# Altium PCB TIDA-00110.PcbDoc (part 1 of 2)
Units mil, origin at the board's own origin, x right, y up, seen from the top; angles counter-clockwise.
Board outline 3543.31 x 1771.65 mil, 4 copper layers (Top Layer, L2_GND-PLANE, L3_PWR-PLANE, Bottom Layer), stack 90 mil thick; 191 components, 98 nets, 449 pads, 138 vias.
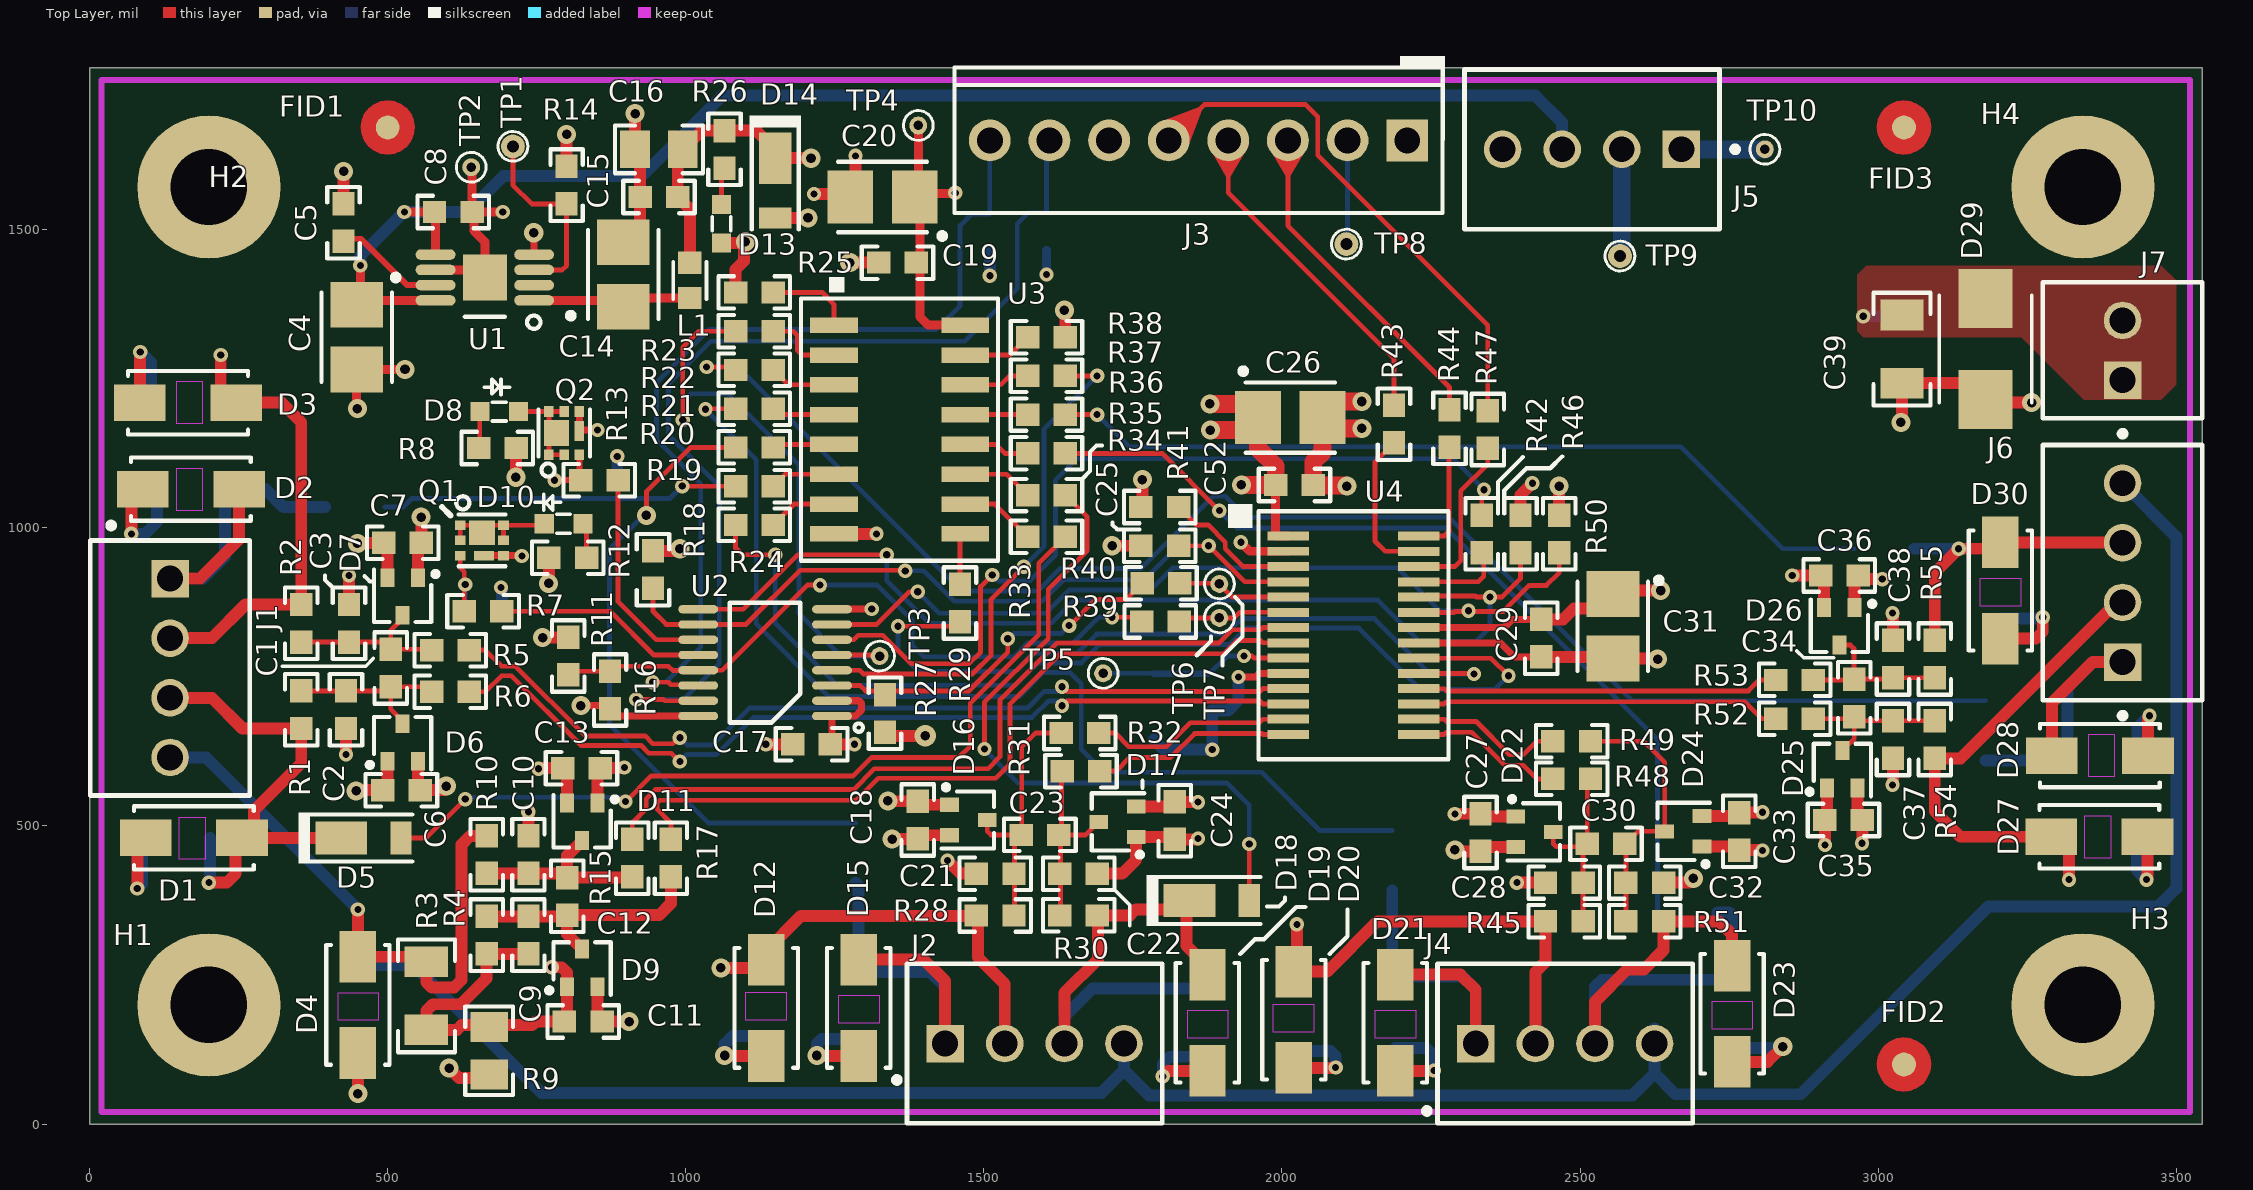
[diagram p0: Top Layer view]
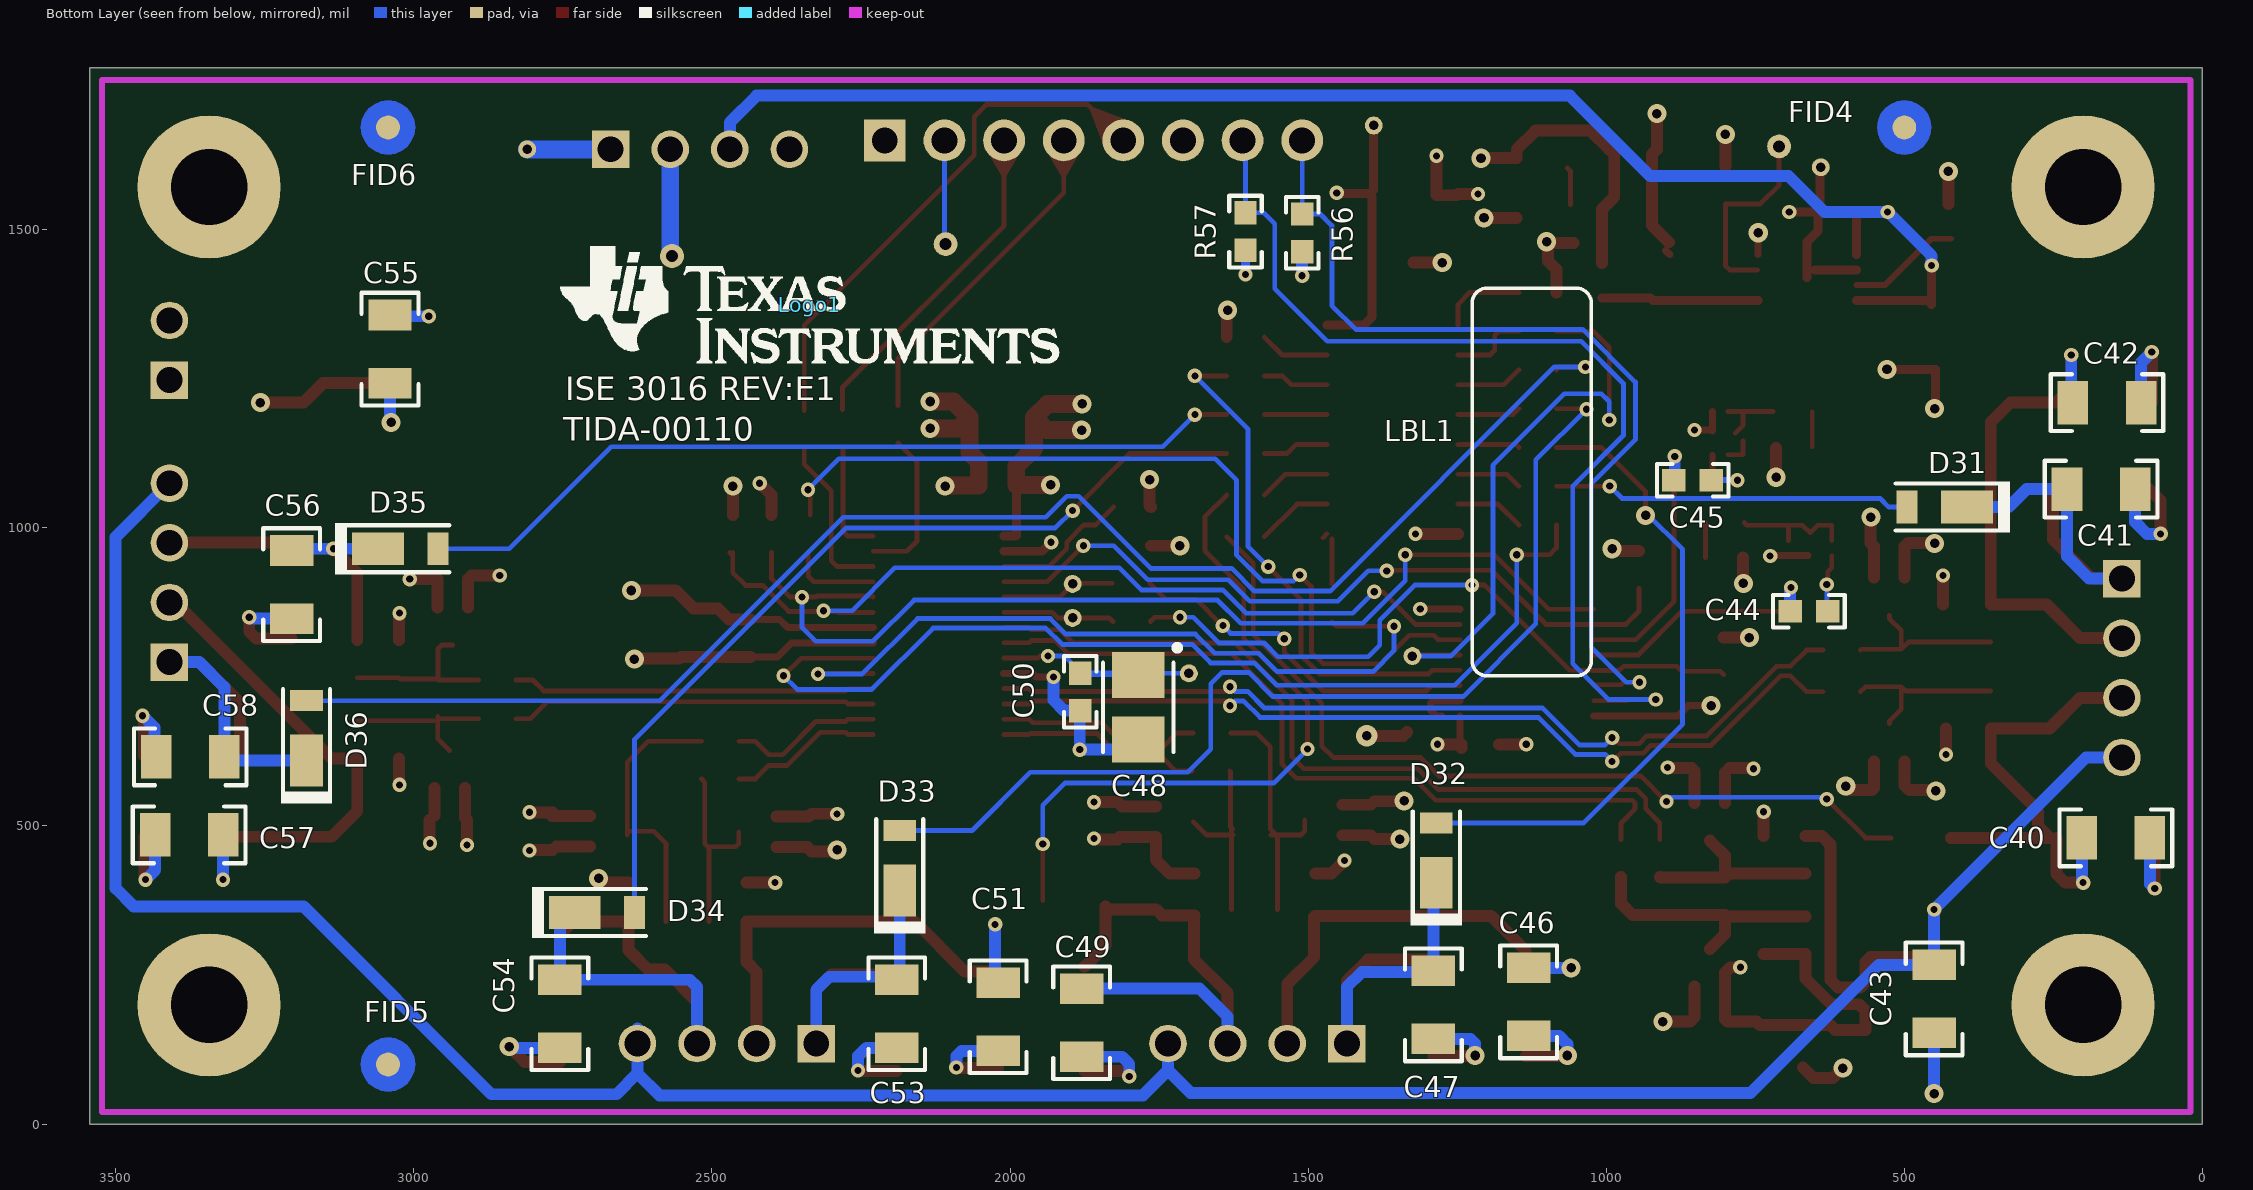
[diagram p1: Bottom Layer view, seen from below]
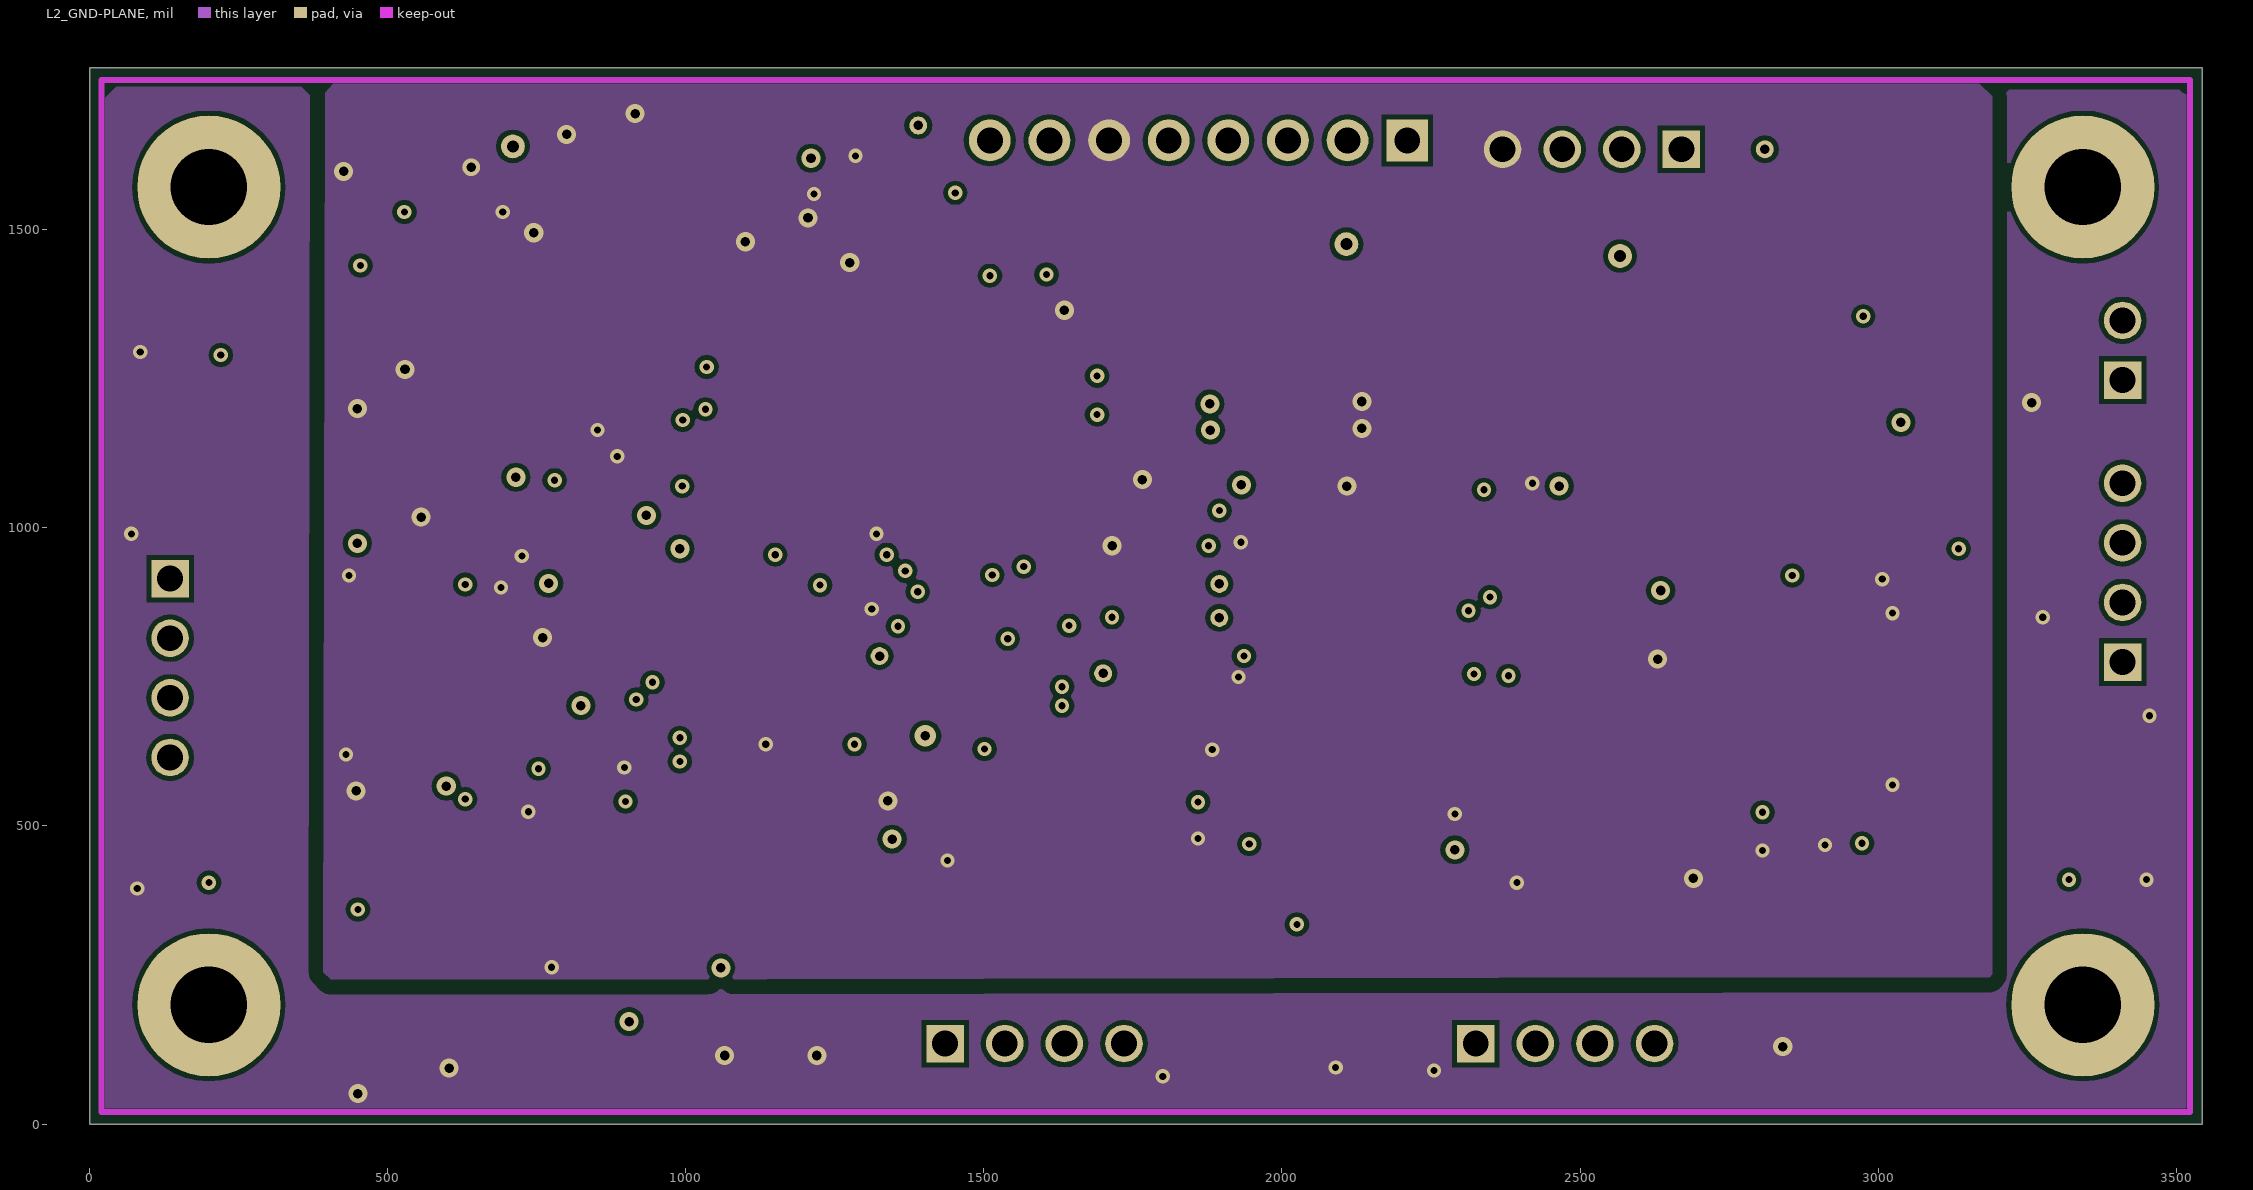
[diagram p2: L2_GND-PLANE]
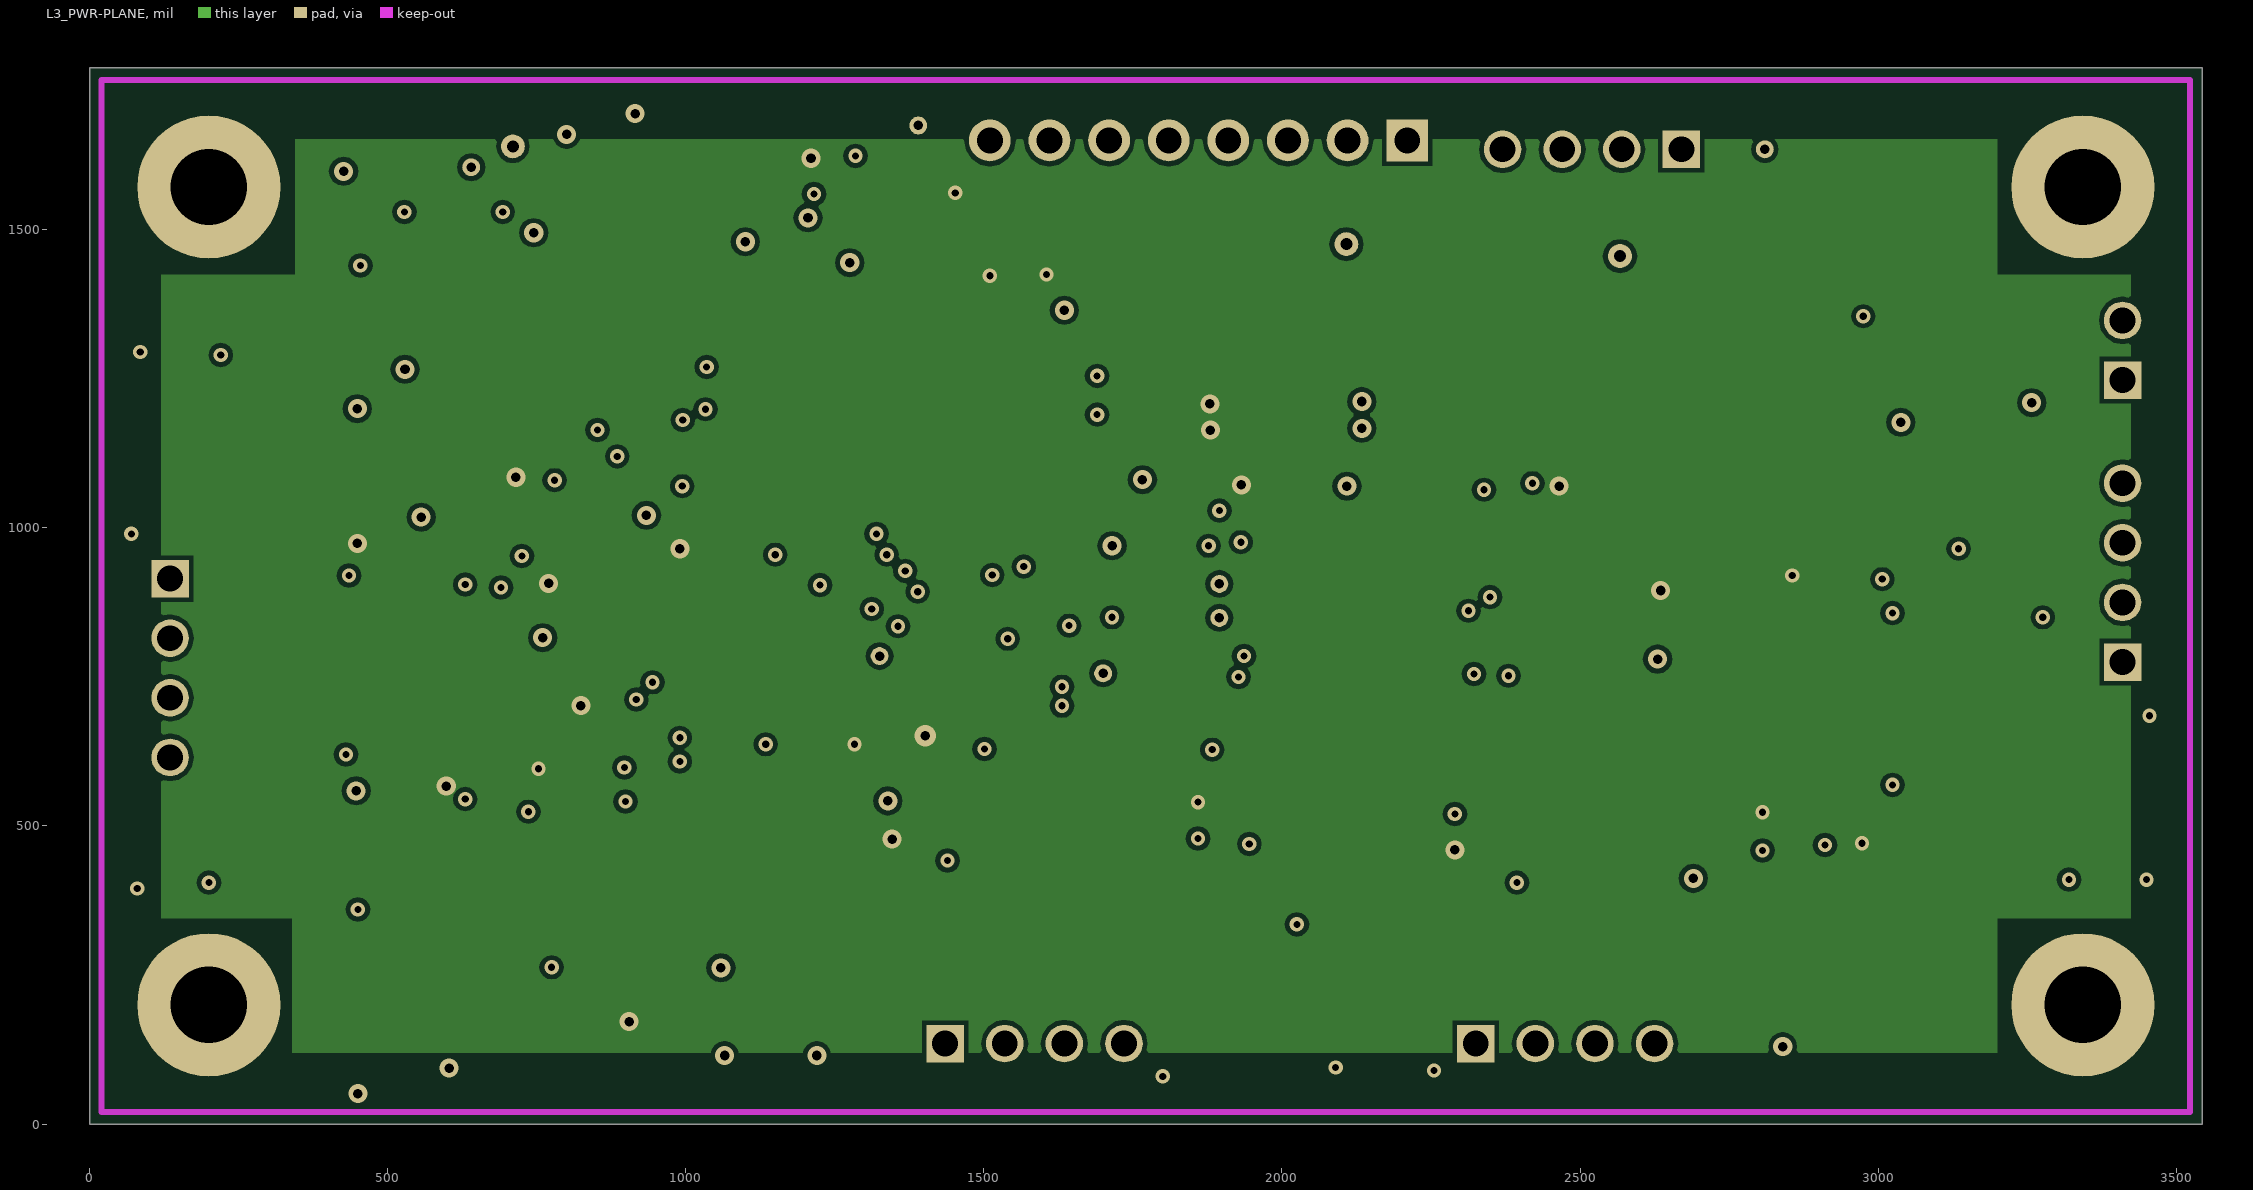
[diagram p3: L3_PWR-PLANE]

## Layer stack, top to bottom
Top Layer: signal copper 1.4
Dielectric: core 59.2, FR-4, Dk 4.8
L2_GND-PLANE: signal copper 1.4
Dielectric: prepreg 12.6, FR-4, Dk 4.8
L3_PWR-PLANE: signal copper 1.4
Dielectric: core 12.6, FR-4, Dk 4.8
Bottom Layer: signal copper 1.4

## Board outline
0,0 0,1771.65 3543.31,1771.65 3543.31,0

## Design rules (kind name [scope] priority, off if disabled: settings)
AcuteAngle [All] p1: minimum=4.50000000000000E+0001 checktracksonly=FALSE
AssemblyTestPointUsage [All] p1: valid=2
Clearance "Clearance_U1 Pad to Pad" [InPadClass('Less Than 7.7') vs InPadClass('Less Than 7.7')] p1: gap=7.7
Clearance Clearance_1 [InPolygon vs IsKeepOut] p2: gap=1
Clearance "Clearance_Poly to Poly" [InPolygon vs InPolygon] p3: gap=25
Clearance "Clearance_VIA TO VIA" [IsVia vs IsVia] p4: gap=8
Clearance "Clearance_Via to SMD" [IsVia vs IsSMTPin] p5: gap=8
Clearance Clearance_BoardEdge_MountingHoles [OnCopper and InComponentClass('Mounting Holes') vs IsKeepOut] p6: gap=20
Clearance Clearance_Poly [InPolygon vs IsTrack and IsVia and IsSMTPin and IsThruPin] p7: gap=15
Clearance [All] p8: gap=8
ComponentClearance ComponentClearance_Logo [InComponentClass('Logo')] p1: gap=50 collisioncheckmode=3 verticalgap=10 showdistances=FALSE
ComponentClearance ComponentClearance_ScrewToNut [(HasFootprint('NY PMS 440 0025 PH')) vs (HasFootprint('Keystone_1902C'))] p2: gap=5 collisioncheckmode=3 verticalgap=10 showdistances=FALSE
ComponentClearance ComponentClearance_MountingHoles [InComponentClass('Mounting Holes')] p3: gap=250 collisioncheckmode=3 verticalgap=100000 showdistances=FALSE
ComponentClearance ComponentClearance_SmallPassives [HasFootprint('0201*') or HasFootprint('0402*') or HasFootprint('0508') or HasFootprint('0603*') or HasFootprint('0612') or HasFootprint('0805*') or HasFootprint('0815*') or HasFootprint('0830*') or HasFootprint('1206*') or HasFootprint('1210*') or HasFootprint('1808*') or HasFootprint('1812*') or HasFootprint('1825*') or HasFootprint('2010*') or HasFootprint('2220*') or HasFootprint('2225*') or HasFootprint('2512*') or HasFootprint('2728*') or HasFootprint('3518*') vs HasFootprint('0201*') or HasFootprint('0402*') or HasFootprint('0508') or HasFootprint('0603*') or HasFootprint('0612') or HasFootprint('0805*') or HasFootprint('0815*') or HasFootprint('0830*') or HasFootprint('1206*') or HasFootprint('1210*') or HasFootprint('1808*') or HasFootprint('1812*') or HasFootprint('1825*') or HasFootprint('2010*') or HasFootprint('2220*') or HasFootprint('2225*') or HasFootprint('2512*') or HasFootprint('2728*') or HasFootprint('3518*')] p4: gap=20 collisioncheckmode=3 verticalgap=10 showdistances=FALSE
ComponentClearance ComponentClearance_THtoSMT [IsThruComponent vs IsSMTComponent] p5: gap=100 collisioncheckmode=3 verticalgap=30 showdistances=FALSE
ComponentClearance ComponentClearance_THtoTH [IsThruComponent vs IsThruComponent] p6: gap=118.11 collisioncheckmode=3 verticalgap=30 showdistances=FALSE
ComponentClearance [All] p7: gap=40 collisioncheckmode=3 verticalgap=10 showdistances=FALSE
DiffPairsRouting DiffPair_DiffPairsRouting [InDifferentialPair ('J1')] p1: maxlimit=10 minlimit=8 mostfreqgap=8 maxuncoupledlength=500
DiffPairsRouting [All] p2: maxlimit=100 minlimit=10 mostfreqgap=10 maxuncoupledlength=1000
FabricationTestPointUsage TestPointUsage [All] p1: valid=2 allowmultiple=FALSE
FabricationTestpoint Testpoint [All] p1: side=3 testpointundercomponent=TRUE minsize=40 maxsize=100 preferedsize=60 minholesize=0 maxholesize=40 preferedholesize=32 testpointgrid=1 allowsidetop=TRUE allowsidebottom=TRUE usegrid=TRUE gridtolerance=0.01
FanoutControl Fanout_LCC [IsLCC] p1: bgadir=Out bgaviamode=Centered fanoutstyle=Auto fanoutdirection=Alternating viagrid=1 // Fanout_LCC (Default Rule)
FanoutControl Fanout_BGA [IsBGA] p2: bgadir=Out bgaviamode=Centered fanoutstyle=Auto fanoutdirection=Alternating viagrid=1 // Fanout_BGA (Default Rule)
FanoutControl Fanout_Default [All] p4: bgadir=Out bgaviamode=Centered fanoutstyle=Auto fanoutdirection=Alternating viagrid=1 // Fanout_Default (Default Rule)
FanoutControl Fanout_Small [(CompPinCount < 5)] p5: bgadir=Out bgaviamode=Centered fanoutstyle=Auto fanoutdirection=OutThenIn viagrid=1 // Fanout_Small (Default Rule)
HoleSize [All] p1: absolutevalues=TRUE maxlimit=251 minlimit=7.8 maxpercent=80.000 minpercent=20.000
MatchedLengths DiffPair_MatchedLengths [InDifferentialPair ('J1')] p1: tolerance=1000 checknetsindiffpair=TRUE checkdiffpairvsdiffpair=TRUE checkothers=TRUE
MinimumAnnularRing MinimumAnnularRing_ThermalPadVias [IsVia and InAnyComponent] p1: minimumring=5.91
MinimumAnnularRing [All] p2: minimumring=6
MinimumSolderMaskSliver MinimumSolderMaskSliver_Logo [InComponentClass('Logo') vs InComponentClass('Logo')] p1: minsoldermaskwidth=0.7
MinimumSolderMaskSliver [All] p2: minsoldermaskwidth=3.94
PlaneClearance [All] p1: clearance=16
PlaneConnect [All] p1: planeconnectstyle=Direct reliefexpansion=10 reliefentries=4 reliefconductorwidth=10 reliefairgap=10
PolygonConnect [All] p1: connectstyle=Direct reliefconductorwidth=10 reliefentries=4 polygonreliefangle="90 Angle"
RoutingVias RoutingVias_PWR [InNetClass('PWR')] p1: holewidth=16 width=32 viastyle="Through Hole" minholewidth=12 minwidth=24 maxholewidth=20 maxwidth=40
RoutingVias [InNetClass('All Nets')] p2: holewidth=12 width=24 viastyle="Through Hole" minholewidth=12 minwidth=24 maxholewidth=20 maxwidth=40
RoutingVias ThermalPadVias [IsVia and InAnyComponent] p3: holewidth=7.87 width=19.68 viastyle="Through Hole" minholewidth=7.87 minwidth=19.68 maxholewidth=12.99 maxwidth=23.62
SMDToCorner [All] p1: distance=30000
SilkToSilkClearance [All] p1: silktosilkclearance=5
SilkscreenOverComponentPads [All] p1 off: minsilkscreentomaskgap=5
SolderMaskExpansion [All] p1: expansion=2.5
Width DiffPair_Width [InDifferentialPair('J1')] p1: maxlimit=10 minlimit=8 preferedwidth=8
Width Width_PWR [InNetClass('PWR')] p2: maxlimit=100 minlimit=8 preferedwidth=20
Width [All] p3: maxlimit=100 minlimit=6 preferedwidth=8 checkconnectedcopper=TRUE
13 further rules are at their usual default settings.

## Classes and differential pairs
component class "Mounting Holes": H1 H2 H3 H4
component class Label: LBL1
component class AssemblyNote: ZZ1 ZZ2 ZZ3 ZZ4
component class "Pg7 Hardware": FID1 FID2 FID3 FID4 FID5 FID6 H1 H2 H3 H4 LBL1 Logo1 ZZ1 ZZ2 ZZ3 ZZ4
component class Logo: Logo1
pad class "Less Than 7.7": U1-1 U1-2 U1-3 U1-4 U1-5 U1-6 U1-7 U1-8
component class "Pg3 CH1-CH3 RTD INTERFACE": C1 C2 C3 C6 C7 C18 C21 C22 C23 C24 C27 C28 C30 C32 C33 C40 C41 C42 C46 C47 C49 C51 C53 C54 D1 D2 D3 D5 D6 D7 D12 D15 D16 D17 D18 D19 D20 D21 D22 D23 D24 D31 D32 D33 D34 J1 J2 J4 R1 R2 R5 R6 R28 R30 R31 R32 R45 R48 R49 R51
component class "Pg4 CH4 RTD INTERFACE": C9 C10 C11 C12 C13 C34 C35 C36 C37 C38 C39 C43 C55 C56 C57 C58 D4 D9 D11 D25 D26 D27 D28 D29 D30 D35 D36 J6 J7 R3 R4 R9 R10 R15 R17 R52 R53 R54 R55
component class "Pg5 ADC + MULTIPLEXER": ` C19 C20 C25 C26 C29 C31 C48 C50 C52 J3 R18 R19 R20 R21 R22 R23 R24 R25 R29 R33 R34 R35 R36 R37 R38 R39 R40 R41 R42 R43 R44 R46 R47 R50 R56 R57 TP2 TP5 TP6 TP7 TP8 U3 U4
component class "Pg6 I2C EXPANDER + POWER SUPPLY": C4 C5 C8 C14 C15 C16 C17 C44 C45 D8 D10 D13 D14 J5 L1 Q1 Q2 R7 R8 R11 R12 R13 R14 R16 R26 R27 TP1 TP3 TP4 TP9 TP10 U1 U2

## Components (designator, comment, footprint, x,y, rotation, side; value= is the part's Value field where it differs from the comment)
C1 "C1608X7R1H473K" 0603 505,765 r270 top (schematic designator C5)
C2 "C1608X8R1H472K" 0603 430,695 r270 top (schematic designator C6)
C3 "C1608X8R1H472K" 0603 435,840 r270 top
C4 "F931C106KBA" 3528-21 448,1320 r270 top (schematic designator C51)
C5 "06031C102JAT2A" 0603 426,1512 r90 top (schematic designator C41)
C6 "06035C104KAT2A" 0603 523,560 r180 top (schematic designator C2)
C7 "06035C104KAT2A" 0603 525,975 r0 top (schematic designator C1)
C8 "06035C104KAT2A" 0603 610,1530 r180 top (schematic designator C52)
C9 "C0603C332K5RACTU" 0603 736,317 r270 top (schematic designator C40)
C10 "C0603C332K5RACTU" 0603 736,452 r270 top (schematic designator C35)
C11 "06035C104KAT2A" 0603 828,172 r180 top (schematic designator C33)
C12 "GRM188R71H333KA61D" 0603 801,382 r270 top (schematic designator C36)
C13 "06035C104KAT2A" 0603 825,597 r0 top (schematic designator C34)
C14 "F931C106KBA" 3528-21 895,1425 r90 top (schematic designator C55)
C15 "06035C104KAT2A" 0603 955,1555 r0 top (schematic designator C43)
C16 "C2012X5R1H475K125AB" 0805_HV 955,1635 r180 top (schematic designator C12)
C17 "06035C104KAT2A" 0603 1211,637 r180 top (schematic designator C10)
C18 "06035C104KAT2A" 0603 1389,510 r90 top (schematic designator C9)
C19 "06035C104KAT2A" 0603 1355,1445 r180 top (schematic designator C29)
C20 "F931C106KBA" 3528-21 1330,1555 r180 top (schematic designator C48)
C21 "C1608X8R1H472K" 0603 1519,420 r0 top (schematic designator C11)
C22 "C1608X8R1H472K" 0603 1659,420 r0 top (schematic designator C14)
C23 "C1608X7R1H473K" 0603 1594,485 r0 top (schematic designator C13)
C24 "06035C104KAT2A" 0603 1820,509 r270 top (schematic designator C10)
C25 "06035C104KAT2A" 0603 1795,970 r180 top (schematic designator C43)
C26 "F931C106KBA" 3528-21 2014,1185 r0 top (schematic designator C41)
C27 "06035C104KAT2A" 0603 2333,489 r90 top (schematic designator C17)
C28 "C1608X8R1H472K" 0603 2473.5,405 r0 top (schematic designator C19)
C29 "06035C104KAT2A" 0603 2435,815 r270 top (schematic designator C7)
C30 "C1608X7R1H473K" 0603 2543.5,470 r0 top (schematic designator C21)
C31 "F931C106KBA" 3528-21 2555,835 r270 top (schematic designator C45)
C32 "C1608X8R1H472K" 0603 2608.5,405 r0 top (schematic designator C22)
C33 "06035C104KAT2A" 0603 2767,491 r270 top (schematic designator C18)
C34 "C1608X7R1H473K" 0603 2960,715 r90 top (schematic designator C29)
C35 "06035C104KAT2A" 0603 2942,510 r180 top (schematic designator C25)
C36 "06035C104KAT2A" 0603 2935,920 r0 top (schematic designator C26)
C37 "C1608X8R1H472K" 0603 3025,645 r90 top (schematic designator C27)
C38 "C1608X8R1H472K" 0603 3025,780 r90 top (schematic designator C30)
C39 "202R18W102KV4E" 1206 3040,1300 r90 top
C40 "CC1206KRX7R0BB102" 1206 145,480 r0 bottom (schematic designator C7)
C41 "CC1206KRX7R0BB102" 1206 170,1065 r0 bottom (schematic designator C8)
C42 "CC1206KRX7R0BB102" 1206 160,1210 r180 bottom (schematic designator C4)
C43 "CC1206KRX7R0BB102" 1206 450,210 r90 bottom (schematic designator C37)
C44 "06033C104JAT2A" 0603 660,860 r0 bottom (schematic designator C58)
C45 "06033C104JAT2A" 0603 855,1080 r0 bottom (schematic designator C9)
C46 "CC1206KRX7R0BB102" 1206 1130,205 r270 bottom (schematic designator C12)
C47 "CC1206KRX7R0BB102" 1206 1290,200 r90 bottom (schematic designator C16)
C48 "F931C106KBA" 3528-21 1785,699 r270 bottom (schematic designator C46)
C49 "CC1206KRX7R0BB102" 1206 1880,170 r90 bottom (schematic designator C15)
C50 "06035C104KAT2A" 0603 1882,725 r270 bottom (schematic designator C47)
C51 "CC1206KRX7R0BB102" 1206 2020,180 r270 bottom (schematic designator C20)
C52 "06035C104KAT2A" 0603 2021,1072 r0 top (schematic designator C42)
C53 "CC1206KRX7R0BB102" 1206 2190,185 r90 bottom (schematic designator C24)
C54 "CC1206KRX7R0BB102" 1206 2755,185 r90 bottom (schematic designator C23)
C55 "202R18W102KV4E" 1206 3040,1300 r90 bottom (schematic designator C38)
C56 "CC1206KRX7R0BB102" 1206 3205,905 r90 bottom (schematic designator C31)
C57 "CC1206KRX7R0BB102" 1206 3377,485 r0 bottom (schematic designator C28)
C58 "CC1206KRX7R0BB102" 1206 3375,616 r180 bottom (schematic designator C32)
D1 "P4SMA13CA" DIO_DO214AC_SMA_BI 175,480 r180 top (schematic designator D6)
D2 "P4SMA13CA" DIO_DO214AC_SMA_BI 170,1065 r180 top (schematic designator D7)
D3 "P4SMA13CA" DIO_DO214AC_SMA_BI 165,1210 r0 top
D4 "P4SMA13CA" DIO_DO214AC_SMA_BI 450,200 r270 top (schematic designator D31)
D5 "DFLS1200-7" powerDI123 472,480 r0 top (schematic designator D1)
D6 "DESD1P0RFW-7" SOT-323 525,640 r90 top (schematic designator D5)
D7 "DESD1P0RFW-7" SOT-323 525,885 r270 top (schematic designator D4)
D8 "LED_LG L29K-G2J1-24-Z" LED0603AA 687,1195 r180 top (schematic designator D33)
D9 "DESD1P0RFW-7" SOT-323 826,262 r90 top (schematic designator D32)
D10 "LED_LG L29K-G2J1-24-Z" LED0603AA 795,1007 r0 top (schematic designator D34)
D11 "DESD1P0RFW-7" SOT-323 826,507 r270 top (schematic designator D29)
D12 "P4SMA13CA" DIO_DO214AC_SMA_BI 1135,195 r90 top (schematic designator D10)
D13 "LED_LG L29K-G2J1-24-Z" LED0603AA 1060,1510 r90 top (schematic designator D36)
D14 "PTZTE253.6B" powerDI123 1150,1570 r270 top (schematic designator D35)
D15 "P4SMA13CA" DIO_DO214AC_SMA_BI 1290,195 r270 top (schematic designator D14)
D16 "DESD1P0RFW-7" SOT-323 1474,510 r0 top (schematic designator D11)
D17 "DESD1P0RFW-7" SOT-323 1724,507 r180 top (schematic designator D12)
D18 "DFLS1200-7" powerDI123 1895,375 r0 top (schematic designator D8)
D19 "P4SMA13CA" DIO_DO214AC_SMA_BI 1875,170 r270 top (schematic designator D13)
D20 "P4SMA13CA" DIO_DO214AC_SMA_BI 2020,175 r90 top (schematic designator D17)
D21 "P4SMA13CA" DIO_DO214AC_SMA_BI 2190,170 r270 top
D22 "DESD1P0RFW-7" SOT-323 2423.5,490 r0 top (schematic designator D18)
D23 "P4SMA13CA" DIO_DO214AC_SMA_BI 2755,185 r270 top (schematic designator D20)
D24 "DESD1P0RFW-7" SOT-323 2673,491 r180 top (schematic designator D19)
D25 "DESD1P0RFW-7" SOT-323 2940,595 r90 top
D26 "DESD1P0RFW-7" SOT-323 2935,835 r270 top
D27 "P4SMA13CA" DIO_DO214AC_SMA_BI 3371,482 r180 top (schematic designator D24)
D28 "P4SMA13CA" DIO_DO214AC_SMA_BI 3372,618 r0 top
D29 "SMBJ18CA" DIO_SMB_BIAAAA 3180,1300 r90 top
D30 "P4SMA13CA" DIO_DO214AC_SMA_BI 3205,895 r270 top (schematic designator D27)
D31 "DFLS1200-7" powerDI123 445,1035 r0 bottom (schematic designator D2)
D32 "DFLS1200-7" powerDI123 1285,455 r90 bottom (schematic designator D9)
D33 "DFLS1200-7" powerDI123 2185,442 r90 bottom (schematic designator D16)
D34 "DFLS1200-7" powerDI123 2680,355 r180 bottom (schematic designator D15)
D35 "DFLS1200-7" powerDI123 3010,965 r180 bottom (schematic designator D22)
D36 "DFLS1200-7" powerDI123 3180,660 r90 bottom (schematic designator D23)
FID1 "Fiducial40_80" FID_TOP_40_80BA 500,1671.65 r90 top (schematic designator FID5)
FID2 "Fiducial40_80" FID_TOP_40_80BA 3043.31,100 r90 top (schematic designator FID4)
FID3 "Fiducial40_80" FID_TOP_40_80BA 3043.31,1671.66 r90 top
FID4 "Fiducial40_80" FID_TOP_40_80BA 500,1671.67 r90 bottom (schematic designator FID1)
FID5 "Fiducial40_80" FID_TOP_40_80BA 3043.31,100 r90 bottom (schematic designator FID6)
FID6 "Fiducial40_80" FID_TOP_40_80BA 3043.31,1671.66 r90 bottom (schematic designator FID2)
H1 "NY PMS 440 0025 PH" "NY PMS 440 0025 PH" 200,200 r0 top (schematic designator H4)
H2 "NY PMS 440 0025 PH" "NY PMS 440 0025 PH" 200,1571.66 r0 top (schematic designator H3)
H3 "NY PMS 440 0025 PH" "NY PMS 440 0025 PH" 3343.31,200 r90 top (schematic designator H1)
H4 "NY PMS 440 0025 PH" "NY PMS 440 0025 PH" 3343.31,1571.66 r0 top (schematic designator H2)
J1 "282834-4" TEC_282834-4 135,765 r270 top
J2 "282834-4" TEC_282834-4 1585,135 r0 top
J3 "1725711" CONN_1725711 1860,1650 r180 top (schematic designator J6)
J4 "282834-4" TEC_282834-4 2475,135 r0 top (schematic designator J3)
J5 "282834-4" TEC_282834-4 2520,1635 r180 top (schematic designator J7)
J6 "282834-4" TEC_282834-4 3410,925 r90 top (schematic designator J4)
J7 "282834-2" TEC_282834-2 3410,1298 r90 top (schematic designator J5)
L1 "1000 OHM" FB0603 1007,1415 r90 top
LBL1 "Size: 0.65\" x 0.20 \"" Label_650x200 1125,1077 r270 bottom
Logo1 "Texas Instruments" TI_Stacked_SolderMask_Small 2336,1374 r180 bottom
Q1 "CSD17571Q2" SON_CSD17571Q2 658,979 r270 top (schematic designator Q2)
Q2 "CSD17571Q2" SON_CSD17571Q2 796,1159 r0 top (schematic designator Q1)
R1 "RG1608P-4121-B-T5" 0603 355,695 r270 top (schematic designator R4)
R2 "RG1608P-4121-B-T5" 0603 355,840 r90 top
R3 "TNPW12062K00BEEA" 1206 565,215 r90 top (schematic designator R19)
R4 "RG1608P-472-B-T5" 0603 666,317 r270 top (schematic designator R21)
R5 "CRCW0603249RFKEA" 0603 605,795 r180 top (schematic designator R1)
R6 "CRCW0603249RFKEA" 0603 605,725 r180 top (schematic designator R3)
R7 "CRCW0603300RJNEA" 0603 660,860 r180 top (schematic designator R60)
R8 "CRCW0603300RJNEA" 0603 684,1134 r0 top (schematic designator R55)
R9 "RC0805JR-070RL" 0805_HV 670,123 r90 top (schematic designator R22)
R10 "RG1608P-472-B-T5" 0603 666,452 r90 top (schematic designator R18)
R11 "CRCW060310K0JNEA" 0603 803,785 r270 top (schematic designator R54)
R12 "CRCW0603300RJNEA" 0603 802,950 r180 top (schematic designator R56)
R13 "CRCW0603300RJNEA" 0603 855,1080 r180 top (schematic designator R59)
R14 "CRCW06030000Z0EA" 0603 800,1575 r270 top (schematic designator R57)
R15 "CRCW0603249RFKEA" 0603 910,446 r270 top (schematic designator R17)
R16 "CRCW060310K0JNEA" 0603 873,728 r270 top (schematic designator R53)
R17 "CRCW0603249RFKEA" 0603 975,446 r270 top (schematic designator R20)
R18 "CRCW060310K0JNEA" 0603 945,930 r270 top (schematic designator R29)
R19 "CRCW06030000Z0EA" 0603 1115,1070 r0 top (schematic designator R47)
R20 "CRCW06030000Z0EA" 0603 1115,1135 r0 top (schematic designator R45)
R21 "CRCW06030000Z0EA" 0603 1115,1200 r0 top (schematic designator R43)
R22 "CRCW06030000Z0EA" 0603 1115,1265 r0 top (schematic designator R41)
R23 "CRCW0603100RFKEA" 0603 1115,1330 r0 top (schematic designator R39)
R24 "CRCW06030000Z0EA" 0603 1115,1005 r0 top (schematic designator R49)
R25 "CRCW060310K0JNEA" 0603 1115,1395 r180 top (schematic designator R38)
R26 "CRCW06031K20JNEAHP" 0603 1065,1635 r90 top (schematic designator R58)
R27 "CRCW060310K0JNEA" 0603 1334,689 r270 top (schematic designator R52)
R28 "RG1608P-4121-B-T5" 0603 1519,350 r180 top (schematic designator R6)
R29 "CRCW06030000Z0EA" 0603 1460,874 r270 top (schematic designator R51)
R30 "RG1608P-4121-B-T5" 0603 1659,350 r0 top (schematic designator R8)
R31 "CRCW0603249RFKEA" 0603 1663,592 r180 top (schematic designator R7)
R32 "CRCW0603249RFKEA" 0603 1661,656 r180 top (schematic designator R5)
R33 "CRCW06030000Z0EA" 0603 1605,985 r0 top (schematic designator R50)
R34 "CRCW06030000Z0EA" 0603 1605,1055 r0 top (schematic designator R48)
R35 "CRCW06030000Z0EA" 0603 1605,1125 r0 top (schematic designator R46)
R36 "CRCW06030000Z0EA" 0603 1605,1190 r0 top (schematic designator R44)
R37 "CRCW0603100RFKEA" 0603 1605,1255 r0 top (schematic designator R42)
R38 "CRCW060310K0JNEA" 0603 1605,1320 r180 top (schematic designator R40)
R39 "CRCW0603100RFKEA" 0603 1796,843 r0 top (schematic designator R34)
R40 "CRCW0603100RFKEA" 0603 1797,907 r0 top (schematic designator R31)
R41 "CRCW060310K0JNEA" 0603 1795,1035 r180 top (schematic designator R27)
R42 "CRCW0603100RFKEA" 0603 2335,990 r90 top (schematic designator R30)
R43 "CRCW0603100RFKEA" 0603 2188,1174 r90 top (schematic designator R26)
R44 "CRCW0603100RFKEA" 0603 2281,1167 r90 top (schematic designator R23)
R45 "RG1608P-4121-B-T5" 0603 2473.5,340 r180 top (schematic designator R10)
R46 "CRCW060310K0JNEA" 0603 2400,990 r270 top (schematic designator R32)
R47 "CRCW0603100RFKEA" 0603 2345,1165 r90 top (schematic designator R28)
R48 "CRCW0603249RFKEA" 0603 2486,579 r0 top (schematic designator R9)
R49 "CRCW0603249RFKEA" 0603 2486,642 r0 top (schematic designator R11)
R50 "CRCW060310K0JNEA" 0603 2465,990 r270 top (schematic designator R35)
R51 "RG1608P-4121-B-T5" 0603 2608.5,340 r0 top (schematic designator R12)
R52 "CRCW0603249RFKEA" 0603 2860,680 r0 top (schematic designator R13)
R53 "CRCW0603249RFKEA" 0603 2860,745 r0 top (schematic designator R15)
R54 "RG1608P-4121-B-T5" 0603 3095,645 r270 top (schematic designator R14)
R55 "RG1608P-4121-B-T5" 0603 3095,780 r90 top (schematic designator R16)
R56 "RC0603JR-072KL" 0603 1510,1495 r270 bottom (schematic designator R36)
R57 "RC0603JR-072KL" 0603 1605,1497 r270 bottom (schematic designator R33)
TP1 "TP-038" TP1_PD40_D0.5_S50#1 710,1640 r90 top (schematic designator TP8)
TP2 "TP-038" TP1_PD40_D0.5_S50#2 640,1605 r90 top (schematic designator TP4)
TP3 "TP-038" TP1_PD40_D0.5_S50#2 1325,785 r90 top (schematic designator TP5)
TP4 "TP-038" TP1_PD40_D0.5_S50#2 1390,1675 r90 top (schematic designator TP9)
TP5 "TP-038" TP1_PD40_D0.5_S50#2 1700,756 r90 top (schematic designator TP3)
TP6 "TP-038" TP1_PD40_D0.5_S50#2 1895,849 r90 top (schematic designator TP2)
TP7 "TP-038" TP1_PD40_D0.5_S50#2 1895,906 r90 top (schematic designator TP1)
TP8 "TP-038" TP1_PD40_D0.5_S50#1 2108,1476 r90 top (schematic designator TP10)
TP9 "TP-038" TP1_PD40_D0.5_S50#1 2567,1456 r90 top (schematic designator TP7)
TP10 "TP-038" TP1_PD40_D0.5_S50#2 2810,1635 r90 top (schematic designator TP6)
U1 "TPS7A1633DGNR" DGN0008C_N 663,1420 r180 top (schematic designator U4)
U2 "TCA6408APWR" PW0016A_N 1133,774 r180 top (schematic designator U3)
U3 "TS3A5017D" SO16 1358.5,1165 r0 top (schematic designator U2)
U4 "ADS1248IPW" PW28 2120,820 r0 top (schematic designator U1)
ZZ1 "These assemblies must comply with workmanship standards IPC-A-610 Class 2, unless otherwise specified." AssemblyNote 347,2198 r0 top (schematic designator ZZ4)
ZZ2 "These assemblies must be clean and free from flux and all contaminants. Use of no clean flux is not acceptable." AssemblyNote 347,2286.56 r0 top (schematic designator ZZ3)
ZZ3 "These assemblies are ESD sensitive, ESD precautions shall be observed." AssemblyNote 347,2375.11 r0 top (schematic designator ZZ2)
ZZ4 "This Assembly Note is for PCB labels only" AssemblyNoteLabel 345,2460 r0 top (schematic designator ZZ1)

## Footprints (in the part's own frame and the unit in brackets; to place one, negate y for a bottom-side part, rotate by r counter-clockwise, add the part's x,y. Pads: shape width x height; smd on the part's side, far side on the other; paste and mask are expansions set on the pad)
0603 [mm] "0603 from SM-752 data"
  rect 1x0.95 smd: 1(-0.8,0) 2(0.8,0)
  silkscreen extent -1.52,-0.69 1.52,0.69, body extent -0.87,-0.47 0.87,0.47, height 0.85
0805_HV [mil] "0805 with 30mil clearance between pads"
  rect 50x63 smd: 1(-40,0) 2(40,0)
  silkscreen extent -74,-40 74,40, body extent -43,-29 43,29, height 43
1206 [mm] "1206 from SM-752 data"
  rect 1.3x1.85 smd: 1(-1.45,0) 2(1.45,0)
  silkscreen extent -2.4,-1.21 2.4,1.21, body extent -1.7,-0.9 1.7,0.9, height 1.35
3528-21 [mm] "Medium Density IPC, based on SM-782 section 8.4"
  rect 1.95x2.25 smd: 1(-1.375,0) 2(1.375,0)
  silkscreen extent -2.66,-1.5 1.9,1.79, body extent -1.85,-1.5 1.85,1.5, height 2.1
AssemblyNote [mil] "Assembly Note"
AssemblyNoteLabel [mil] "Assembly Note for PCB Labels"
CONN_1725711 [mm] "Phoenix Contact"
  rect 1.78x1.78 hole 1.1: 1(-8.89,0)
  round 1.78 hole 1.1: 2(-6.35,0) 3(-3.81,0) 4(-1.27,0) 5(1.27,0) 6(3.81,0) 7(6.35,0) 8(8.89,0)
  silkscreen extent -10.49,-3.6 10.4,3.1, body extent -10.39,-3.1 10.39,3.1, height 8.52
DGN0008C_N [mm] "TSOP, 8-Leads, Body 3x3mm, Pitch 0.65mm, Thermal Pad 1.98x1.88mm, IPC Medium Density"
  oval 1.7x0.45 smd mask+0.05: 1(-2.1,0.975) 2(-2.1,0.325) 3(-2.1,-0.325) 4(-2.1,-0.975) 5(2.1,-0.975) 6(2.1,-0.325) 7(2.1,0.325) 8(2.1,0.975)
  rect 1.88x1.98 smd mask+0.07: 9(0,0)
  silkscreen extent -0.85,1.68 0.85,1.68, body extent -2.45,-1.5 2.45,1.5, height 0.94
DIO_DO214AC_SMA_BI [mm] "DIODE, BIDIRECTIONAL, DO-214AC, 2-PIN"
  rect 2.2x1.55 smd: 1(-2.05,0) 2(2.05,0)
  Top Layer keep-out region: -0.506,-0.869 0.637,-0.869 0.637,0.891 -0.506,0.891
  silkscreen extent -2.55,-1.35 2.55,1.35, body extent -2.55,-1.33 2.55,1.33, height 2.29
DIO_SMB_BIAAAA [mm]
  rect 2.5x2.3 smd: 1(-2.15,0) 2(2.15,0)
  silkscreen extent -2.28,-1.97 2.29,1.97
FB0603 [mm]
  rect 0.95x1 smd: 1(-0.75,0) 2(0.75,0)
  silkscreen extent -0.8,-0.7 0.8,0.7
FID_TOP_40_80BA [mil]
  round 40 smd mask+20: 1(0,0)
  Top Layer region: 45.39,0 43.84,11.75 39.31,22.69 32.09,32.09 22.69,39.31 11.75,43.84 0,45.39 -11.75,43.84 -22.69,39.31 -32.09,32.09 -39.31,22.69 -43.84,11.75 -45.39,0 -43.84,-11.75 -39.31,-22.69 -32.09,-32.09 -22.69,-39.31 -11.75,-43.84 0,-45.39 11.75,-43.84 22.69,-39.31 32.09,-32.09 39.31,-22.69 43.84,-11.75
Label_650x200 [mil] "Thermal Transfer Label"
  silkscreen extent -325,-100 325,100, body extent -326,-101 326,101, height 1
LED0603AA [mil]
  rect 32x32 smd: 1(-32.48,0) 2(32.48,0)
  silkscreen extent -11,-16 11,16
"NY PMS 440 0025 PH" [mil] "4-40 nylon screw and mounting hole"
  round 240 hole 128: 1(0,0)
  body extent -130,-130 130,130, height 106
powerDI123 [mm] "Diodes Inc recommended land pattern, document number DS30628 Rev. 6-2"
  rect 2.2x1.4 smd: 1(-1.275,0)
  rect 0.9x1.4 smd: 2(1.275,0)
  silkscreen extent -3.1,-1.09 1.76,1.09, body extent -2.38,-0.97 1.52,0.96, height 1
PW0016A_N [mm] "TSOP, 16-Leads, Body 5x4.4mm, Pitch 0.65mm, IPC Medium Density"
  oval 1.7x0.35 smd: 1(-2.85,2.275) 2(-2.85,1.625) 3(-2.85,0.975) 4(-2.85,0.325) 5(-2.85,-0.325) 6(-2.85,-0.975) 7(-2.85,-1.625) 8(-2.85,-2.275) 9(2.85,-2.275) 10(2.85,-1.625) 11(2.85,-0.975) 12(2.85,-0.325) 13(2.85,0.325) 14(2.85,0.975) 15(2.85,1.625) 16(2.85,2.275)
  silkscreen extent -1.5,-2.55 1.5,2.55, body extent -3.21,-2.5 3.21,2.5, height 0.98
PW28 [mil]
  rect 70x15 smd: 1(-109.5,166.4) 2(-109.5,140.8) 3(-109.5,115.2) 4(-109.5,89.6) 5(-109.5,64) 6(-109.5,38.4) 7(-109.5,12.8) 8(-109.5,-12.8) 9(-109.5,-38.4) 10(-109.5,-64) 11(-109.5,-89.6) 12(-109.5,-115.2) 13(-109.5,-140.8) 14(-109.5,-166.4) 15(109.5,-166.5) 16(109.5,-140.9) 17(109.5,-115.3) 18(109.5,-89.7) 19(109.5,-64.1) 20(109.5,-38.5) 21(109.5,-12.9) 22(109.5,12.7) 23(109.5,38.3) 24(109.5,63.9) 25(109.5,89.5) 26(109.5,115.1) 27(109.5,140.7) 28(109.5,166.4)
  silkscreen extent -210,-208 160,220
SO16 [mil]
  rect 80x26 smd: 1(-110,175) 2(-110,125) 3(-110,75) 4(-110,25) 5(-110,-25) 6(-110,-75) 7(-110,-125) 8(-110,-175) 9(110,-175) 10(110,-125) 11(110,-75) 12(110,-25) 13(110,25) 14(110,75) 15(110,125) 16(110,175)
  silkscreen extent -165,-220 165,255
SON_CSD17571Q2 [mm] "SON, MOSFET, N-CH, 30V, 22A, SON 2X2 MM"
  rect 0.4x0.455 smd mask+0.038: 1(-0.65,-0.923) 2(0,-0.923) 5(0,0.923) 6(-0.65,0.923)
  rect 0.4x0.455 smd: 3(0.65,-0.923) 4(0.65,0.923)
  rect 0.4x0.85 smd mask+0.038: 7(0.65,0.096)
  rect 1.05x1.1 smd mask+0.038: 8(-0.325,0)
  silkscreen extent -1.88,-1.09 1.1,1, body extent -1,-1 1,0.97, height 0.85
SOT-323 [mm] "Zetex recommended land pattern.  March 2007"
  rect 0.8x0.6 smd: 1(-0.8,0.65) 2(-0.8,-0.65) 3(0.8,0)
  silkscreen extent -1.14,-1.22 1.09,1.49, body extent -1.13,-1.13 1.12,1.12, height 1.13
TEC_282834-2 [mm] "TEC"
  rect 1.6x1.6 hole 1.1: 1(-1.27,0)
  round 1.6 hole 1.1: 2(1.27,0)
  silkscreen extent -3.66,-3.4 2.9,3.4, body extent -2.77,-3.25 2.77,3.25, height 10.01
TEC_282834-4 [mm] "TEC"
  rect 1.6x1.6 hole 1.1: 1(-3.81,0)
  round 1.6 hole 1.1: 2(-1.27,0) 3(1.27,0) 4(3.81,0)
  silkscreen extent -6.17,-3.4 5.44,3.4, body extent -5.31,-3.25 5.31,3.25, height 10.02
TI_Stacked_SolderMask_Small [mil]
  silkscreen extent -418,-98 418,98
TP1_PD40_D0.5_S50#1 [mil]
  round 40 hole 20: 1(0,0)
  silkscreen extent -25,-25 25,25
TP1_PD40_D0.5_S50#2 [mil]
  round 30 hole 16: 1(0,0)
  silkscreen extent -25,-25 25,25

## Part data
C1 C23 C30 C34: "CAP, CERM, 0.047uF, 50V, +/-10%, X7R, 0603"
C2 C3 C21 C22 C28 C32 C37 C38: "CAP, CERM, 4700pF, 50V, +/-10%, X8R, 0603"
C4 C14 C20 C26 C31 C48: library part 293D106X9016B2TE3, "CAP, TA, 10 µF, 16 V, +/- 10%, 2 ohm, SMD"
C5: "CAP, CERM, 1000pF, 100V, +/-5%, X7R, 0603"
C6 C7 C11 C13 C18 C24 C25 C27 C33 C35 C36: library part C0603C104K5RACTU, "CAP, CERM, 0.1uF, 50V, +/-10%, X7R, 0603"
C8 C15 C17 C19 C29 C50 C52: "CAP, CERM, 0.1uF, 50V, +/-10%, X7R, 0603"
C9 C10: "CAP, CERM, 3300pF, 50V, +/-10%, X7R, 0603"
C12: "CAP, CERM, 0.033uF, 50V, +/-10%, X7R, 0603"
C16: "CAP, CERM, 4.7uF, 50V, +/-10%, X5R, 0805"
C39 C55: "CAP, CERM, 1000pF, 2KV 10% X7R 1206"
C40 C41 C42 C43 C46 C47 C49 C51 C53 C54 C56 C57 C58: library part 202R18W102KV4E, "CAP CER 1000PF 100V 10% X7R 1206"
C44 C45: "CAP, CERM, 0.1uF, 25V, +/-5%, X7R, 0603"
D1 D2 D3 D4 D12 D15 D19 D20 D21 D23 D27 D28 D30: library part SMBJ18CA, "TVS DIODE 11.1VWM 18.2VC SMD"
D5 D18 D31 D32 D33 D34 D35 D36: "Diode, Schotky, 200V, 1A, PowerDI123"
D6 D7 D9 D11 D16 D17 D22 D24 D25 D26: library part BAV99WT1G, "TVS DIODE,70VVVM,8VC,SOT-323"
D8 D10 D13: "LED, SMARTLED, GREEN, 570NM,0603"
D14: library part PTZTE255.6B, "DIODE ZENER 3.8V 1W PMDS"
D29: "TVS 18 VOLT 600 WATT BI-DIR SMB"
FID1 FID2 FID3 FID4 FID5 FID6: library part Fiducial40_0
H1 H2 H3 H4: "Machine Screw, Round, #4-40 x 1/4, Nylon, Philips panhead"
J1 J2 J4 J5 J6: "Receptacle, 100mil, 4X1 TH"
J3: "Terminal Block, 8x1, 2.54 mm, TH"
J7: "Terminal Block, 2x1, 2.54mm, TH"
L1: library part MMZ1608B102C, "FERRITE CHIP 1000 OHM 300MA 0603"
LBL1: library part THT-14-423-10, "Thermal Transfer Printable Labels, 0.650\" W x 0.200\" H - 10,000 per roll"
Logo1: library part TI_Logo, "Texas Instrument Corporate Signature"
Q1 Q2: "MOSFET, N-CH, 30V, 22A, SON 2X2 MM"
R1 R2 R28 R30 R45 R51 R54 R55: "RES, 4.12k ohm, 0.1%, 0.1W, 0603"
R3: library part CRCW12062K49FKEA, "RES 2K OHM 1/4W 0.1% 1206"
R4 R10: "RES, 4.70k ohm, 0.1%, 0.1W, 0603"
R5 R6 R15 R17 R31 R32 R48 R49 R52 R53: "RES, 249, 1%, 0.1 W, 0603"
R7 R8 R12 R13: "RES, 300 ohm, 5%, 0.1W, 0603"
R9: "RES, 0 ohm, 5%, 0.125W, 0805"
R11 R16 R18 R25 R27 R38 R41 R46 R50: "RES, 10 k, 5%, 0.1 W, 0603"
R14 R19 R20 R21 R22 R24 R29 R33 R34 R35 R36: "RES, 0, 5%, 0.1 W, 0603"
R23 R37 R39 R40 R42 R43 R44 R47: "RES, 100, 1%, 0.1 W, 0603"
R26: library part CRCW06031K20JNEA, "RES, 1.2 k, 5%, 0.1 W, 0603"
R56 R57: "RES, 2.0 k, 5%, 0.1 W, 0603"
TP1 TP2 TP3 TP4 TP5 TP6 TP7 TP8 TP9 TP10: "Test Point 40mil pad 20mil drill"
U1: "Single Output LDO, 100 mA, Fixed 3.3 V Output, 3 to 60 V Input, with Enable and Power Good, 8-pin MSOP (DGN), -40 to 125 degC, Green (RoHS & no Sb/Br)"
U2: "Low-Voltage 8-Bit I2C and SMBus I/O Expander, 1.65 to 5.5 V, -40 to 85 degC, 16-pin TSSOP (PW), Green (RoHS & no Sb/Br)"
U3: "IC, Dual, 14 Ohms SP4T Analog Switch"
U4: "IC, 24-Bit A-D Converters for Temperature Sensors"
ZZ1 ZZ2 ZZ3: library part AssemblyNote
ZZ4: library part AssemblyNoteLabel

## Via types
v1: diameter 24, hole 12, Top Layer to Bottom Layer, tented both sides, 92 vias
v2: diameter 32, hole 16, Top Layer to Bottom Layer, tented both sides, 45 vias
v3: diameter 36, hole 16, Top Layer to Bottom Layer, tented both sides, 1 vias

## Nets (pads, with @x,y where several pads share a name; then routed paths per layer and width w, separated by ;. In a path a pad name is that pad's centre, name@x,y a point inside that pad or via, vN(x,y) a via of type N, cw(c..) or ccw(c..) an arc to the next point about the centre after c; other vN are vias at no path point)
+3.3V: C6.1 C7.1 C11.1 C13.1 C15.2 C16.1 C17.1 C18.1 C19.1 C20.1 C24.1 C26.1 C27.1 C29.1 C31.1 C33.1 C35.1 C36.1 C52.1 D6.2 D7.2 D9.2 D11.2 D14.1 D16.2 D17.2 D22.2 D24.2 D25.2 D26.2 L1.2 R8.2 R12.2 R16.2 R18.1 R26.2 R27.2 R50.1 R56.2 R57.2 TP4.1 U2.1 U2.2 U2.16 U3.16 U4.1 U4.22 | length 3513.1
  Top Layer w12: v2(824,702) 862.5,702 880.07,684.43 U2.16@1020.8,684.43 ; C17.1@1245.2,637 U2.1@1245.2,684.43 ; U2.2@1245.2,710.02 1289.98,710.02 1295,705 1295,695 1284.43,684.43 U2.1@1275.43,684.43 ; U4.22@2229.5,832.7 2372.7,832.7 2386.5,846.5 C29.1@2435,846.5
  Top Layer w15: TP4.1@1390,1675 1390,1567.13 1396.13,1561 1451,1561 v1(1452,1562) ; C20.1@1392.5,1555 1392.5,1424 1392.5,1422 1392.5,1354.5 1407,1340 U3.16@1468.5,1340 ; C52.1@1989.5,1072 1989.5,987.5 1990.6,986.4 U4.1@2010.5,986.4
  Top Layer w20: v2(449,974) 450,975 C7.1@493.5,975 ; D7.2@499.41,916.5 C7.1@499.41,969.09 ; D6.2@550.59,608.5 550.59,563.91 C6.1@554.5,560 595,560 598.18,563.18 v2(598.18,566.92) ; v2(715,1085) 715.5,1085.5 R8.2@715.5,1134 ; v1(753,596) 754,597 C13.1@793.5,597 ; v2(770,907) 770.5,907.5 R12.2@770.5,950 ; D11.2@800.41,538.5 C13.1@800.41,590.09 ; D9.2@851.59,230.5 851.59,179.91 C11.1@859.5,172 v2(905,172) ; R18.1@945,961.5 986.5,961.5 v2(990,965) ; L1.2@1007,1444.53 1007,1534.5 C15.2@986.5,1555 986.5,1626.5 C16.1@995,1635 1026.5,1666.5 R26.2@1065,1666.5 1118.5,1666.5 1150,1635 D14.1@1150,1620.2 1209.8,1620.2 v2(1210,1620) ; C17.1@1242.5,630.5 C17.1@1243,630.5 ; C17.1@1242.5,637 1245.2,637 v1(1283,637) ; R27.2@1334,657.5 1340.5,651 v3(1402,651) ; v2(1346,478) 1346.5,478.5 C18.1@1389,478.5 ; C18.1@1394.91,484.41 D16.2@1442.5,484.41 ; D17.2@1755.5,532.59 1812.09,532.59 C24.1@1820,540.5 1858.5,540.5 v1(1859,540) ; v2(2290,460) 2292.5,457.5 C27.1@2333,457.5 2339.91,464.41 D22.2@2392.01,464.41 ; C29.1@2435,846.5 2471.5,846.5 2490,865 2530.87,865 C31.1@2555,889.13 2560.87,895 v2(2635,895) ; R50.1@2465,1021.5 v2(2465,1070) ; D24.2@2704.5,516.59 C33.1@2768.41,516.59 ; C33.1@2767,522.5 2805.5,522.5 v1(2806,523) ; v1(2856,920) C36.1@2903.5,920 ; D26.2@2909.41,866.5 C36.1@2909.41,914.09 ; C35.1@2965.59,517.91 D25.2@2965.59,563.5 ; v1(2973,471) 2973.5,471.5 C35.1@2973.5,510
  Top Layer w30: v2(1879,1208) 1936.87,1208 C26.1@1959.87,1185 ; v2(1880,1164) 1938.87,1164 C26.1@1959.87,1185 ; v2(1932,1072) C52.1@1989.5,1072 1989.5,1103.5 1959.87,1133.13 C26.1@1959.87,1185
  Bottom Layer w15: v1(1605,1425) R57.2@1605,1465.5
  Bottom Layer w20: v1(1510,1423) R56.2@1510,1463.5
+6V: C4.1 C8.2 J5.3 U1.5 U1.8 | length 2524.9
  Top Layer w15: v1(454.13,1440) 454.13,1375 460.75,1381.61 U1.8@580.32,1381.61 ; v1(528,1530) C8.2@578.5,1530 C8.2@581.5,1530 ; U1.5@580.32,1458.39 C8.2@580.32,1528.82
  Bottom Layer w20: v1(454.13,1440) 454.13,1456.13 v1(528,1530) 634,1530 694,1590 926,1590 1061,1725 2425,1725 2470,1680 J5.3@2470,1635
/INT1: R11.2 R16.1 R39.1 U2.13 | length 1134.2
  Top Layer w8: R11.2@803,753.5 808.99,759.5 R16.1@873,759.5 881.5,768 970.94,768 977.94,761 1020.59,761 U2.13@1020.8,761.2 1061.2,761.2 1204,904 v1(1225,904) ; v1(1715,850) 1757.5,850 R39.1@1764.5,843
  Bottom Layer w8: v1(1225,904) 1320.94,904 1380,844.94 1380,803 1399,784 1551,784 1574,807 1650,807 1693,850 v1(1715,850)
ADC_CS/: R46.2 U2.9 U4.24 | length 1773.1
  Top Layer w8: U2.9@1020.8,863.57 1096.57,863.57 1188,955 v1(1337,955) ; U4.24@2229.5,883.9 2231.5,885.9 2324,885.9 2326,883.9 v1(2348.9,883.9) 2368.9,883.9 2400,915 R46.2@2400,958.5
  Bottom Layer w8: v1(1337,955) 1337,911.06 1408.06,840 1613,840 1652,879 2161,879 2230,810 2326,810 2348.9,832.9 v1(2348.9,883.9)
ADC_RDY/: R42.2 U2.6 | length 1471.5
  Top Layer w8: U2.6@1245.2,812.39 1282,812.39 1289.61,820 1330,820 1378,772 1475,772 1494.5,791.5 1494.5,901.5 v1(1514,921) ; R42.2@2335,1021.5 2335,1060 v1(2339,1064)
  Bottom Layer w8: v1(1514,921) 1524,911 1576.94,911 1620,954.06 1620,1080 1656,1116 2287,1116 v1(2339,1064)
ADC_RESET/: C25.1 R18.2 U2.10 U4.4 | length 1294.4
  Top Layer w8: R18.2@945,898.5 945,860 967.02,837.98 U2.10@1020.8,837.98 1100.98,837.98 1192,929 1366.94,929 v1(1368,927.94) ; C25.1@1826.5,970 v1(1877,970) ; v1@1885,970 v1(1877,970) ; U4.4@2010.5,909.6 1937.4,909.6 v1(1877,970)
  Bottom Layer w8: v1(1368,927.94) 1399,927.94 1449.94,877 1598,877 1634,913 1769,913 1826,970 v1(1877,970)
ADC_START: R50.2 U2.7 U4.23 | length 1470.5
  Top Layer w8: U2.7@1245.2,837.98 1319.92,837.98 1374.94,893 v1(1389,893) ; U4.23@2229.5,858.3 2288.4,858.3 2290,859.9 2371.4,859.9 2415,903.5 2443.5,903.5 2465,925 R50.2@2465,953.5 ; R50.2@2465,958.5 R50.2@2465,953.5 ; R50.2@2470,958.5 R50.2@2465,953.5
  Bottom Layer w8: v1(1389,893) 1425,857 1604,857 1643,896 1780,896 1817,933 2193,933 2265,861 v1(2313,861)
GND_EARTH: C39.2 C55.2 D29.2 J7.1 J7.2 | length 65.9
  Bottom Layer w20: v1(2975,1355) 3037.91,1355 C55.2@3040,1357.09
IEXC1: R24.1 U4.20 | length 1752.5
  Top Layer w8: R24.1@1083.5,1005 1083.5,966.5 1095,955 v1(1150,955) ; U4.20@2229.5,781.5 2350.5,781.5 v1(2380,752)
  Bottom Layer w8: v1(1150,955) 1150,840 1254,736 1553,736 1590.6,773.6 1663.6,773.6 1694.52,804.52 1912.52,804.52 1940,832 2129,832 2232,729 2357,729 v1(2380,752)
IEXC2: R29.2 U4.19 | length 1296.9
  Top Layer w8: v1(1356,835) 1452.5,835 R29.2@1460,842.5 ; U4.19@2229.5,755.9 2321.1,755.9 v1(2322,755)
  Bottom Layer w8: v1(1356,835) 1356,794 1391,759 1552,759 1582.6,789.6 1656.6,789.6 1689,822 1906.18,822 1932.18,848 2155,848 2248,755 v1(2322,755)
LED1: R13.1 U2.11 | length 364.4
  Top Layer w8: R13.1@886.5,1080 886.5,876.5 950.61,812.39 U2.11@1020.8,812.39
LED2: R7.1 U2.12 | length 359.6
  Top Layer w8: R7.1@691.5,860 873,860 946.2,786.8 U2.12@1020.8,786.8
NetC1_1: C1.1 C3.2 D7.3 R2.1 R5.2 | length 289.4
  Top Layer w8: R2.1@355,808.5 C3.2@435,808.5 492.99,808.5 C1.1@505,796.5 ; D7.3@525,853.5 525,848 505,828 C1.1@505,796.5 ; R5.2@573.5,795 572.01,796.5 C1.1@505,796.5
NetC1_2: C1.2 C2.1 D6.3 R1.1 R6.2 | length 295.2
  Top Layer w8: R1.1@355,726.5 C2.1@430,726.5 497.99,726.5 C1.2@505,733.5 ; D6.3@525,671.5 525,676 505,696 C1.2@505,733.5 ; R6.2@573.5,725 565,733.5 C1.2@505,733.5
NetC5_1: C5.1 U1.7 | length 191.1
  Top Layer w10: C5.1@421.5,1485 455,1485 532.8,1407.2 U1.7@580.32,1407.2
NetC9_1: C9.1 C12.2 D9.3 R4.1 R17.2 | length 429.8
  Top Layer w8: C12.2@798.99,348.5 C12.2@801,350.5
  Top Layer w20: R4.1@666,348.5 C9.1@736,348.5 C12.2@798.99,348.5 ; D9.3@826,293.5 801,318.5 C12.2@801,350.5 955.5,350.5 975,370 R17.2@975,414.5
NetC10_2: C10.2 C12.1 D11.3 R10.1 R15.2 | length 377.7
  Top Layer w8: C10.2@736,420.5 C12.1@793.99,420.5
  Top Layer w20: R10.1@666,420.5 793.99,420.5 C12.1@801,413.5 ; D11.3@826,475.5 801,450.5 C12.1@801,413.5 ; R15.2@910,414.5 908.99,413.5 C12.1@801,413.5
NetC14_1: C14.1 L1.1 U1.1 | length 262.9
  Top Layer w15: U1.1@745.68,1381.61 921.39,1381.61 925.24,1385.47 L1.1@1007,1385.47
NetC21_2: C21.2 C23.1 D16.3 R28.1 R32.2 | length 431.4
  Top Layer w8: D16.3@1505.5,510 1505.5,491.5 1512,485 C23.1@1553.5,485 ; R28.1@1551.5,360 1551.5,430 1551.5,482.99 C23.1@1553.5,485 ; C23.1@1562.5,485 C23.1@1553.5,485 ; R32.2@1629.5,656 1587,656 1563.5,632.5 1563.5,495 C23.1@1553.5,485
NetC22_1: C22.1 C23.2 D17.3 R30.1 R31.2 | length 311
  Top Layer w8: C23.2@1625.5,485 C23.2@1628.5,485 ; R30.1@1628.5,360 C23.2@1628.5,485 ; R31.2@1631.5,592 1630,590.5 1630,498.5 1626.5,495 1628.5,492.99 C23.2@1628.5,485 ; D17.3@1692.5,507 1670.5,485 C23.2@1628.5,485
NetC28_2: C28.2 C30.1 D22.3 R45.1 R48.2 | length 318.3
  Top Layer w8: D22.3@2455,490 2455,470 2460,465 C30.1@2507.01,465 ; R45.1@2505,340 C28.2@2505,405 2505,462.99 C30.1@2507.01,465 ; R48.2@2517.5,579 2512.01,573.51 C30.1@2512.01,470 C30.1@2507.01,465
NetC30_2: C30.2 C32.1 D24.3 R49.2 R51.1 | length 465
  Top Layer w8: R49.2@2517.5,642 2607,642 2642.01,606.99 D24.3@2642.01,485 ; R51.1@2577.01,340 C32.1@2577.01,405 2577.01,467.99 2576,469 2598,491 D24.3@2641.5,491
NetC34_1: C34.1 C37.2 D25.3 R52.2 R54.1 | length 258.3
  Top Layer w8: R52.2@2891.5,680 C34.1@2956.5,680 ; D25.3@2940,626.5 2960,646.5 C34.1@2960,683.5 ; C34.1@2967.01,676.5 C37.2@3025,676.5 R54.1@3095,676.5
NetC34_2: C34.2 C38.1 D26.3 R53.2 R55.1 | length 283.2
  Top Layer w8: R53.2@2891.5,745 2958.5,745 C34.2@2960,746.5 ; D26.3@2935,803.5 2953.5,803.5 2959.5,797.5 2959.5,747 C34.2@2960,746.5 ; R55.1@3095,748.5 C38.1@3025,748.5 3022.99,746.5 C34.2@2960,746.5
NetC40_2: C40.2 D1.1 D5.1 J1.3 R1.2 | length 819.1
  Top Layer w20: J1.3@135,715 205,715 256.5,663.5 R1.2@355,663.5 355,605 275.39,525.39 275.39,499.68 D1.1@255.71,480 D5.1@421.8,480 ; v1(200,405) 230,405 245,420 D1.1@245,480
  Bottom Layer w20: v1(200,405) 202.09,407.09 C40.2@202.09,480
NetC41_2: C41.2 D2.1 D31.1 J1.1 | length 627.7
  Top Layer w20: J1.1@135,915 185,915 250.71,980.71 D2.1@250.71,1065
  Bottom Layer w20: J1.1@135,915 190,915 227.09,952.09 C41.2@227.09,1065 295,1065 325,1035 D31.1@394.8,1035
NetC42_1: C42.1 D3.2 J1.2 R2.2 | length 843.7
  Top Layer w20: J1.2@135,815 205,815 261.5,871.5 R2.2@355,871.5 355,1177 322,1210 D3.2@245.71,1210 220,1235.71 v1(220,1290)
  Bottom Layer w20: C42.1@217.09,1210 220,1212.91 v1(220,1290)
NetC44_1: C44.1 Q1.3 R7.2 | length 141.9
  Top Layer w8: Q1.3@621.68,953.41 621.68,933.32 628.5,926.5 R7.2@628.5,860
  Bottom Layer w8: C44.1@628.5,860 630,861.5 v1(630,905)
NetC45_1: C45.1 Q2.3 R13.2 | length 130.5
  Top Layer w10: v1(780,1080) R13.2@823.5,1080 821.59,1081.91 Q2.3@821.59,1122.68
  Bottom Layer w10: v1(780,1080) C45.1@823.5,1080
